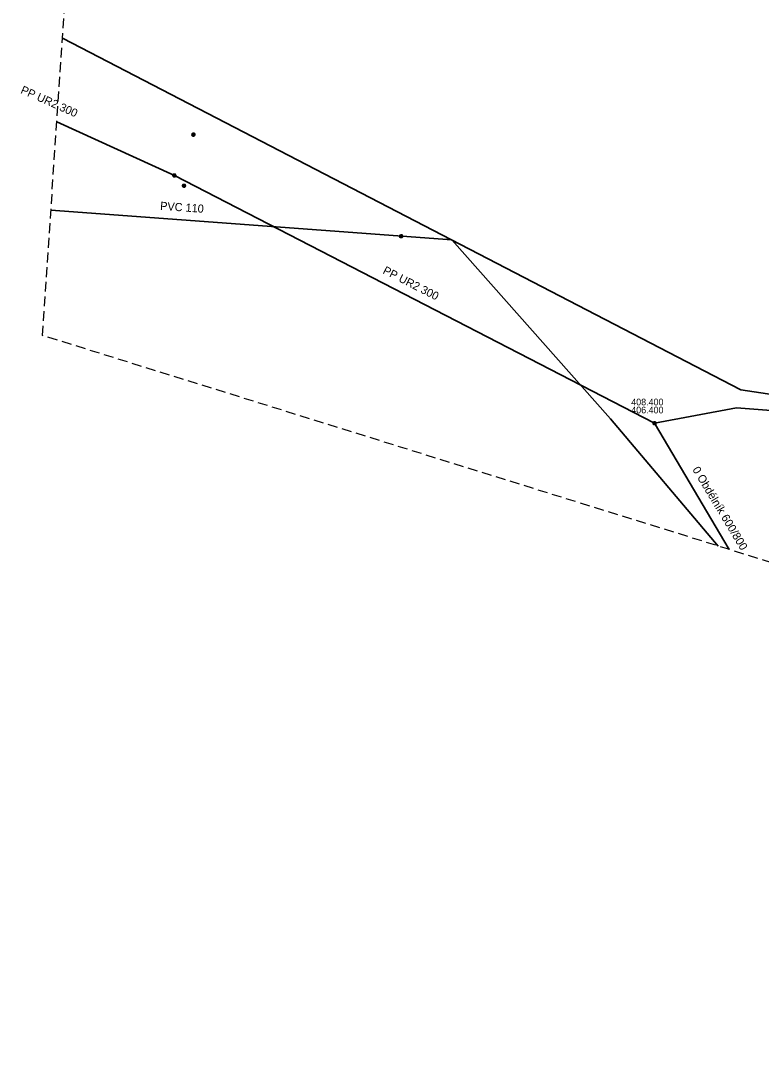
# Model space of a CAD drawing. Extents: x -867104 to -866746, y -1014489 to -1014255.
# Drawn here: x -867103.7 to -867003.8, y -1014488.9 to -1014348.8 of the extents above; entities that cross this region are included whole.
import ezdxf

# ---------------------------------------------------------------- set-up
doc = ezdxf.new("R2010")
doc.units = 0
doc.header["$LTSCALE"] = 0.44
doc.linetypes.add('MEDIUM_DASHED', pattern=[4.5, 3, -1.5])
for name, color, linetype, lineweight in [('1', 7, 'Continuous', 35), ('12', 7, 'Continuous', 13), ('21', 7, 'Continuous', 35), ('25', 7, 'Continuous', 13), ('32', 7, 'Continuous', 13), ('62', 7, 'MEDIUM_DASHED', 25)]:
    doc.layers.add(name, color=color, linetype=linetype, lineweight=lineweight)

msp = doc.modelspace()

# ---------------------------------------------------------------- linework, layer by layer
at = {"layer": '1'}
msp.add_line((-867045.534, -1014378.337), (-867099.611, -1014374.334), dxfattribs=at)
for points in [[(-866877.679, -1014463.149), (-866884.593, -1014451.356), (-866912.586, -1014412.658), (-867006.516, -1014398.571), (-867098.057, -1014351.101)], [(-867009.578, -1014419.65), (-867024.113, -1014402.496), (-867045.534, -1014378.337)]]:
    msp.add_lwpolyline(points, dxfattribs=at)
at = {"layer": '12'}
for points in [[(-867052.127, -1014377.832), (-867052.133, -1014377.78), (-867052.15, -1014377.73), (-867052.179, -1014377.686), (-867052.216, -1014377.649), (-867052.261, -1014377.622), (-867052.311, -1014377.605), (-867052.364, -1014377.601), (-867052.416, -1014377.608), (-867052.465, -1014377.627), (-867052.508, -1014377.656), (-867052.544, -1014377.695), (-867052.57, -1014377.74), (-867052.586, -1014377.791), (-867052.589, -1014377.843), (-867052.581, -1014377.895), (-867052.561, -1014377.944), (-867052.53, -1014377.987), (-867052.491, -1014378.021), (-867052.445, -1014378.047), (-867052.394, -1014378.061), (-867052.341, -1014378.063), (-867052.29, -1014378.053), (-867052.242, -1014378.032), (-867052.199, -1014378.001), (-867052.165, -1014377.96), (-867052.141, -1014377.914), (-867052.129, -1014377.863)], [(-867052.157, -1014377.832), (-867052.163, -1014377.783), (-867052.18, -1014377.737), (-867052.208, -1014377.697), (-867052.245, -1014377.665), (-867052.289, -1014377.643), (-867052.337, -1014377.632), (-867052.386, -1014377.632), (-867052.433, -1014377.645), (-867052.476, -1014377.669), (-867052.512, -1014377.702), (-867052.539, -1014377.743), (-867052.555, -1014377.79), (-867052.559, -1014377.839), (-867052.552, -1014377.887), (-867052.533, -1014377.932), (-867052.503, -1014377.972), (-867052.465, -1014378.003), (-867052.421, -1014378.023), (-867052.373, -1014378.033), (-867052.324, -1014378.031), (-867052.277, -1014378.016), (-867052.234, -1014377.991), (-867052.2, -1014377.957), (-867052.174, -1014377.915), (-867052.16, -1014377.868)], [(-867052.187, -1014377.832), (-867052.193, -1014377.787), (-867052.21, -1014377.745), (-867052.238, -1014377.71), (-867052.274, -1014377.683), (-867052.316, -1014377.666), (-867052.361, -1014377.661), (-867052.406, -1014377.667), (-867052.447, -1014377.686), (-867052.482, -1014377.714), (-867052.509, -1014377.751), (-867052.525, -1014377.793), (-867052.529, -1014377.838), (-867052.522, -1014377.883), (-867052.503, -1014377.924), (-867052.474, -1014377.958), (-867052.437, -1014377.984), (-867052.394, -1014378), (-867052.349, -1014378.003), (-867052.304, -1014377.995), (-867052.264, -1014377.975), (-867052.23, -1014377.946), (-867052.204, -1014377.908), (-867052.19, -1014377.865)], [(-867052.217, -1014377.832), (-867052.222, -1014377.791), (-867052.24, -1014377.754), (-867052.267, -1014377.723), (-867052.302, -1014377.702), (-867052.342, -1014377.691), (-867052.383, -1014377.693), (-867052.422, -1014377.706), (-867052.456, -1014377.73), (-867052.481, -1014377.762), (-867052.496, -1014377.8), (-867052.499, -1014377.841), (-867052.491, -1014377.881), (-867052.471, -1014377.917), (-867052.442, -1014377.946), (-867052.405, -1014377.965), (-867052.365, -1014377.973), (-867052.324, -1014377.969), (-867052.286, -1014377.954), (-867052.254, -1014377.928), (-867052.231, -1014377.894), (-867052.218, -1014377.855)], [(-867052.247, -1014377.832), (-867052.252, -1014377.796), (-867052.27, -1014377.764), (-867052.296, -1014377.739), (-867052.33, -1014377.724), (-867052.366, -1014377.721), (-867052.401, -1014377.729), (-867052.432, -1014377.749), (-867052.455, -1014377.777), (-867052.468, -1014377.811), (-867052.468, -1014377.848), (-867052.457, -1014377.883), (-867052.436, -1014377.912), (-867052.406, -1014377.933), (-867052.371, -1014377.943), (-867052.334, -1014377.941), (-867052.3, -1014377.927), (-867052.273, -1014377.904), (-867052.254, -1014377.872), (-867052.247, -1014377.837)], [(-867052.277, -1014377.832), (-867052.282, -1014377.801), (-867052.299, -1014377.775), (-867052.325, -1014377.758), (-867052.355, -1014377.751), (-867052.386, -1014377.755), (-867052.413, -1014377.772), (-867052.431, -1014377.796), (-867052.439, -1014377.827), (-867052.435, -1014377.857), (-867052.42, -1014377.885), (-867052.396, -1014377.904), (-867052.366, -1014377.913), (-867052.335, -1014377.91), (-867052.307, -1014377.896), (-867052.287, -1014377.872), (-867052.277, -1014377.843)], [(-867052.307, -1014377.832), (-867052.312, -1014377.808), (-867052.329, -1014377.79), (-867052.352, -1014377.781), (-867052.376, -1014377.784), (-867052.397, -1014377.798), (-867052.408, -1014377.82), (-867052.408, -1014377.845), (-867052.396, -1014377.866), (-867052.376, -1014377.88), (-867052.351, -1014377.883), (-867052.328, -1014377.874), (-867052.312, -1014377.856)], [(-867052.337, -1014377.832), (-867052.342, -1014377.817), (-867052.357, -1014377.811), (-867052.372, -1014377.815), (-867052.379, -1014377.829), (-867052.375, -1014377.844), (-867052.362, -1014377.853), (-867052.347, -1014377.85), (-867052.337, -1014377.838)]]:
    msp.add_lwpolyline(points, close=True, dxfattribs=at)
at = {"layer": '21'}
for p, q in [((-867082.957, -1014369.63), (-867098.814, -1014362.42)), ((-867018.151, -1014403.08), (-867082.957, -1014369.63)), ((-867008.073, -1014420.119), (-867018.151, -1014403.08))]:
    msp.add_line(p, q, dxfattribs=at)
msp.add_lwpolyline([(-866953.081, -1014405.138), (-866972.671, -1014403.647), (-866981.237, -1014402.954), (-866985.536, -1014402.661), (-867007.098, -1014400.979), (-867018.151, -1014403.08)], dxfattribs=at)
at = {"layer": '25'}
for points in [[(-867080.159, -1014364.13), (-867080.165, -1014364.078), (-867080.182, -1014364.028), (-867080.211, -1014363.984), (-867080.248, -1014363.947), (-867080.293, -1014363.92), (-867080.343, -1014363.903), (-867080.396, -1014363.899), (-867080.448, -1014363.906), (-867080.497, -1014363.925), (-867080.54, -1014363.954), (-867080.576, -1014363.993), (-867080.602, -1014364.038), (-867080.618, -1014364.089), (-867080.621, -1014364.141), (-867080.613, -1014364.193), (-867080.593, -1014364.242), (-867080.562, -1014364.285), (-867080.523, -1014364.319), (-867080.477, -1014364.345), (-867080.426, -1014364.359), (-867080.373, -1014364.361), (-867080.322, -1014364.351), (-867080.274, -1014364.33), (-867080.231, -1014364.299), (-867080.197, -1014364.258), (-867080.173, -1014364.212), (-867080.161, -1014364.161)], [(-867080.189, -1014364.13), (-867080.195, -1014364.081), (-867080.212, -1014364.035), (-867080.24, -1014363.995), (-867080.277, -1014363.963), (-867080.321, -1014363.941), (-867080.369, -1014363.93), (-867080.418, -1014363.93), (-867080.465, -1014363.943), (-867080.508, -1014363.967), (-867080.544, -1014364), (-867080.571, -1014364.041), (-867080.587, -1014364.088), (-867080.591, -1014364.137), (-867080.584, -1014364.185), (-867080.565, -1014364.23), (-867080.535, -1014364.27), (-867080.497, -1014364.301), (-867080.453, -1014364.321), (-867080.405, -1014364.331), (-867080.356, -1014364.329), (-867080.309, -1014364.314), (-867080.266, -1014364.289), (-867080.232, -1014364.255), (-867080.206, -1014364.213), (-867080.192, -1014364.166)], [(-867080.219, -1014364.13), (-867080.225, -1014364.085), (-867080.242, -1014364.043), (-867080.27, -1014364.008), (-867080.306, -1014363.981), (-867080.348, -1014363.964), (-867080.393, -1014363.959), (-867080.438, -1014363.965), (-867080.479, -1014363.984), (-867080.514, -1014364.012), (-867080.541, -1014364.049), (-867080.557, -1014364.091), (-867080.561, -1014364.136), (-867080.554, -1014364.181), (-867080.535, -1014364.222), (-867080.506, -1014364.256), (-867080.469, -1014364.282), (-867080.426, -1014364.298), (-867080.381, -1014364.301), (-867080.336, -1014364.293), (-867080.296, -1014364.273), (-867080.262, -1014364.244), (-867080.236, -1014364.206), (-867080.222, -1014364.163)], [(-867080.249, -1014364.13), (-867080.254, -1014364.089), (-867080.272, -1014364.052), (-867080.299, -1014364.021), (-867080.334, -1014364), (-867080.374, -1014363.989), (-867080.415, -1014363.991), (-867080.454, -1014364.004), (-867080.488, -1014364.028), (-867080.513, -1014364.06), (-867080.528, -1014364.098), (-867080.531, -1014364.139), (-867080.523, -1014364.179), (-867080.503, -1014364.215), (-867080.474, -1014364.244), (-867080.437, -1014364.263), (-867080.397, -1014364.271), (-867080.356, -1014364.267), (-867080.318, -1014364.252), (-867080.286, -1014364.226), (-867080.263, -1014364.192), (-867080.25, -1014364.153)], [(-867080.279, -1014364.13), (-867080.284, -1014364.094), (-867080.302, -1014364.062), (-867080.328, -1014364.037), (-867080.362, -1014364.022), (-867080.398, -1014364.019), (-867080.433, -1014364.027), (-867080.464, -1014364.047), (-867080.487, -1014364.075), (-867080.5, -1014364.109), (-867080.5, -1014364.146), (-867080.489, -1014364.181), (-867080.468, -1014364.21), (-867080.438, -1014364.231), (-867080.403, -1014364.241), (-867080.366, -1014364.239), (-867080.332, -1014364.225), (-867080.305, -1014364.202), (-867080.286, -1014364.17), (-867080.279, -1014364.135)], [(-867080.309, -1014364.13), (-867080.314, -1014364.099), (-867080.331, -1014364.073), (-867080.357, -1014364.056), (-867080.387, -1014364.049), (-867080.418, -1014364.053), (-867080.445, -1014364.07), (-867080.463, -1014364.094), (-867080.471, -1014364.125), (-867080.467, -1014364.155), (-867080.452, -1014364.183), (-867080.428, -1014364.202), (-867080.398, -1014364.211), (-867080.367, -1014364.208), (-867080.339, -1014364.194), (-867080.319, -1014364.17), (-867080.309, -1014364.141)], [(-867080.339, -1014364.13), (-867080.344, -1014364.106), (-867080.361, -1014364.088), (-867080.384, -1014364.079), (-867080.408, -1014364.082), (-867080.429, -1014364.096), (-867080.44, -1014364.118), (-867080.44, -1014364.143), (-867080.428, -1014364.164), (-867080.408, -1014364.178), (-867080.383, -1014364.181), (-867080.36, -1014364.172), (-867080.344, -1014364.154)], [(-867080.369, -1014364.13), (-867080.374, -1014364.115), (-867080.389, -1014364.109), (-867080.404, -1014364.113), (-867080.411, -1014364.127), (-867080.407, -1014364.142), (-867080.394, -1014364.151), (-867080.379, -1014364.148), (-867080.369, -1014364.136)], [(-867081.419, -1014371.02), (-867081.425, -1014370.968), (-867081.442, -1014370.918), (-867081.471, -1014370.874), (-867081.508, -1014370.837), (-867081.553, -1014370.81), (-867081.603, -1014370.793), (-867081.656, -1014370.789), (-867081.708, -1014370.796), (-867081.757, -1014370.815), (-867081.8, -1014370.844), (-867081.836, -1014370.883), (-867081.862, -1014370.928), (-867081.878, -1014370.979), (-867081.881, -1014371.031), (-867081.873, -1014371.083), (-867081.853, -1014371.132), (-867081.822, -1014371.175), (-867081.783, -1014371.209), (-867081.737, -1014371.235), (-867081.686, -1014371.249), (-867081.633, -1014371.251), (-867081.582, -1014371.241), (-867081.534, -1014371.22), (-867081.491, -1014371.189), (-867081.457, -1014371.148), (-867081.433, -1014371.102), (-867081.421, -1014371.051)], [(-867081.449, -1014371.02), (-867081.455, -1014370.971), (-867081.472, -1014370.925), (-867081.5, -1014370.885), (-867081.537, -1014370.853), (-867081.581, -1014370.831), (-867081.629, -1014370.82), (-867081.678, -1014370.82), (-867081.725, -1014370.833), (-867081.768, -1014370.857), (-867081.804, -1014370.89), (-867081.831, -1014370.931), (-867081.847, -1014370.978), (-867081.851, -1014371.027), (-867081.844, -1014371.075), (-867081.825, -1014371.12), (-867081.795, -1014371.16), (-867081.757, -1014371.191), (-867081.713, -1014371.211), (-867081.665, -1014371.221), (-867081.616, -1014371.219), (-867081.569, -1014371.204), (-867081.526, -1014371.179), (-867081.492, -1014371.145), (-867081.466, -1014371.103), (-867081.452, -1014371.056)], [(-867081.479, -1014371.02), (-867081.485, -1014370.975), (-867081.502, -1014370.933), (-867081.53, -1014370.898), (-867081.566, -1014370.871), (-867081.608, -1014370.854), (-867081.653, -1014370.849), (-867081.698, -1014370.855), (-867081.739, -1014370.874), (-867081.774, -1014370.902), (-867081.801, -1014370.939), (-867081.817, -1014370.981), (-867081.821, -1014371.026), (-867081.814, -1014371.071), (-867081.795, -1014371.112), (-867081.766, -1014371.146), (-867081.729, -1014371.172), (-867081.686, -1014371.188), (-867081.641, -1014371.191), (-867081.596, -1014371.183), (-867081.556, -1014371.163), (-867081.522, -1014371.134), (-867081.496, -1014371.096), (-867081.482, -1014371.053)], [(-867081.509, -1014371.02), (-867081.514, -1014370.979), (-867081.532, -1014370.942), (-867081.559, -1014370.911), (-867081.594, -1014370.89), (-867081.634, -1014370.879), (-867081.675, -1014370.881), (-867081.714, -1014370.894), (-867081.748, -1014370.918), (-867081.773, -1014370.95), (-867081.788, -1014370.988), (-867081.791, -1014371.029), (-867081.783, -1014371.069), (-867081.763, -1014371.105), (-867081.734, -1014371.134), (-867081.697, -1014371.153), (-867081.657, -1014371.161), (-867081.616, -1014371.157), (-867081.578, -1014371.142), (-867081.546, -1014371.116), (-867081.523, -1014371.082), (-867081.51, -1014371.043)], [(-867081.539, -1014371.02), (-867081.544, -1014370.984), (-867081.562, -1014370.952), (-867081.588, -1014370.927), (-867081.622, -1014370.912), (-867081.658, -1014370.909), (-867081.693, -1014370.917), (-867081.724, -1014370.937), (-867081.747, -1014370.965), (-867081.76, -1014370.999), (-867081.76, -1014371.036), (-867081.749, -1014371.071), (-867081.728, -1014371.1), (-867081.698, -1014371.121), (-867081.663, -1014371.131), (-867081.626, -1014371.129), (-867081.592, -1014371.115), (-867081.565, -1014371.092), (-867081.546, -1014371.06), (-867081.539, -1014371.025)], [(-867081.569, -1014371.02), (-867081.574, -1014370.989), (-867081.591, -1014370.963), (-867081.617, -1014370.946), (-867081.647, -1014370.939), (-867081.678, -1014370.943), (-867081.705, -1014370.96), (-867081.723, -1014370.984), (-867081.731, -1014371.015), (-867081.727, -1014371.045), (-867081.712, -1014371.073), (-867081.688, -1014371.092), (-867081.658, -1014371.101), (-867081.627, -1014371.098), (-867081.599, -1014371.084), (-867081.579, -1014371.06), (-867081.569, -1014371.031)], [(-867081.599, -1014371.02), (-867081.604, -1014370.996), (-867081.621, -1014370.978), (-867081.644, -1014370.969), (-867081.668, -1014370.972), (-867081.689, -1014370.986), (-867081.7, -1014371.008), (-867081.7, -1014371.033), (-867081.688, -1014371.054), (-867081.668, -1014371.068), (-867081.643, -1014371.071), (-867081.62, -1014371.062), (-867081.604, -1014371.044)], [(-867081.629, -1014371.02), (-867081.634, -1014371.005), (-867081.649, -1014370.999), (-867081.664, -1014371.003), (-867081.671, -1014371.017), (-867081.667, -1014371.032), (-867081.654, -1014371.041), (-867081.639, -1014371.038), (-867081.629, -1014371.026)]]:
    msp.add_lwpolyline(points, close=True, dxfattribs=at)
at = {"layer": '32'}
for points in [[(-867082.726, -1014369.63), (-867082.732, -1014369.578), (-867082.749, -1014369.528), (-867082.778, -1014369.484), (-867082.815, -1014369.447), (-867082.86, -1014369.42), (-867082.91, -1014369.403), (-867082.963, -1014369.399), (-867083.015, -1014369.406), (-867083.064, -1014369.425), (-867083.107, -1014369.454), (-867083.143, -1014369.493), (-867083.169, -1014369.538), (-867083.185, -1014369.589), (-867083.188, -1014369.641), (-867083.18, -1014369.693), (-867083.16, -1014369.742), (-867083.129, -1014369.785), (-867083.09, -1014369.819), (-867083.044, -1014369.845), (-867082.993, -1014369.859), (-867082.94, -1014369.861), (-867082.889, -1014369.851), (-867082.841, -1014369.83), (-867082.798, -1014369.799), (-867082.764, -1014369.758), (-867082.74, -1014369.712), (-867082.728, -1014369.661)], [(-867082.756, -1014369.63), (-867082.762, -1014369.581), (-867082.779, -1014369.535), (-867082.807, -1014369.495), (-867082.844, -1014369.463), (-867082.888, -1014369.441), (-867082.936, -1014369.43), (-867082.985, -1014369.43), (-867083.032, -1014369.443), (-867083.075, -1014369.467), (-867083.111, -1014369.5), (-867083.138, -1014369.541), (-867083.154, -1014369.588), (-867083.158, -1014369.637), (-867083.151, -1014369.685), (-867083.132, -1014369.73), (-867083.102, -1014369.77), (-867083.064, -1014369.801), (-867083.02, -1014369.821), (-867082.972, -1014369.831), (-867082.923, -1014369.829), (-867082.876, -1014369.814), (-867082.833, -1014369.789), (-867082.799, -1014369.755), (-867082.773, -1014369.713), (-867082.759, -1014369.666)], [(-867082.786, -1014369.63), (-867082.792, -1014369.585), (-867082.809, -1014369.543), (-867082.837, -1014369.508), (-867082.873, -1014369.481), (-867082.915, -1014369.464), (-867082.96, -1014369.459), (-867083.005, -1014369.465), (-867083.046, -1014369.484), (-867083.081, -1014369.512), (-867083.108, -1014369.549), (-867083.124, -1014369.591), (-867083.128, -1014369.636), (-867083.121, -1014369.681), (-867083.102, -1014369.722), (-867083.073, -1014369.756), (-867083.036, -1014369.782), (-867082.993, -1014369.798), (-867082.948, -1014369.801), (-867082.903, -1014369.793), (-867082.863, -1014369.773), (-867082.829, -1014369.744), (-867082.803, -1014369.706), (-867082.789, -1014369.663)], [(-867082.816, -1014369.63), (-867082.821, -1014369.589), (-867082.839, -1014369.552), (-867082.866, -1014369.521), (-867082.901, -1014369.5), (-867082.941, -1014369.489), (-867082.982, -1014369.491), (-867083.021, -1014369.504), (-867083.055, -1014369.528), (-867083.08, -1014369.56), (-867083.095, -1014369.598), (-867083.098, -1014369.639), (-867083.09, -1014369.679), (-867083.07, -1014369.715), (-867083.041, -1014369.744), (-867083.004, -1014369.763), (-867082.964, -1014369.771), (-867082.923, -1014369.767), (-867082.885, -1014369.752), (-867082.853, -1014369.726), (-867082.83, -1014369.692), (-867082.817, -1014369.653)], [(-867082.846, -1014369.63), (-867082.851, -1014369.594), (-867082.869, -1014369.562), (-867082.895, -1014369.537), (-867082.929, -1014369.522), (-867082.965, -1014369.519), (-867083, -1014369.527), (-867083.031, -1014369.547), (-867083.054, -1014369.575), (-867083.067, -1014369.609), (-867083.067, -1014369.646), (-867083.056, -1014369.681), (-867083.035, -1014369.71), (-867083.005, -1014369.731), (-867082.97, -1014369.741), (-867082.933, -1014369.739), (-867082.899, -1014369.725), (-867082.872, -1014369.702), (-867082.853, -1014369.67), (-867082.846, -1014369.635)], [(-867082.876, -1014369.63), (-867082.881, -1014369.599), (-867082.898, -1014369.573), (-867082.924, -1014369.556), (-867082.954, -1014369.549), (-867082.985, -1014369.553), (-867083.012, -1014369.57), (-867083.03, -1014369.594), (-867083.038, -1014369.625), (-867083.034, -1014369.655), (-867083.019, -1014369.683), (-867082.995, -1014369.702), (-867082.965, -1014369.711), (-867082.934, -1014369.708), (-867082.906, -1014369.694), (-867082.886, -1014369.67), (-867082.876, -1014369.641)], [(-867082.906, -1014369.63), (-867082.911, -1014369.606), (-867082.928, -1014369.588), (-867082.951, -1014369.579), (-867082.975, -1014369.582), (-867082.996, -1014369.596), (-867083.007, -1014369.618), (-867083.007, -1014369.643), (-867082.995, -1014369.664), (-867082.975, -1014369.678), (-867082.95, -1014369.681), (-867082.927, -1014369.672), (-867082.911, -1014369.654)], [(-867082.936, -1014369.63), (-867082.941, -1014369.615), (-867082.956, -1014369.609), (-867082.971, -1014369.613), (-867082.978, -1014369.627), (-867082.974, -1014369.642), (-867082.961, -1014369.651), (-867082.946, -1014369.648), (-867082.936, -1014369.636)], [(-867017.919, -1014403.08), (-867017.926, -1014403.028), (-867017.943, -1014402.978), (-867017.972, -1014402.934), (-867018.009, -1014402.897), (-867018.054, -1014402.87), (-867018.103, -1014402.853), (-867018.157, -1014402.849), (-867018.208, -1014402.856), (-867018.257, -1014402.875), (-867018.301, -1014402.904), (-867018.337, -1014402.943), (-867018.363, -1014402.988), (-867018.379, -1014403.039), (-867018.382, -1014403.091), (-867018.374, -1014403.143), (-867018.353, -1014403.192), (-867018.323, -1014403.235), (-867018.284, -1014403.269), (-867018.238, -1014403.295), (-867018.186, -1014403.309), (-867018.134, -1014403.311), (-867018.083, -1014403.301), (-867018.034, -1014403.28), (-867017.992, -1014403.249), (-867017.958, -1014403.208), (-867017.934, -1014403.162), (-867017.921, -1014403.111)], [(-867017.95, -1014403.08), (-867017.956, -1014403.031), (-867017.973, -1014402.985), (-867018, -1014402.945), (-867018.038, -1014402.913), (-867018.081, -1014402.891), (-867018.13, -1014402.88), (-867018.179, -1014402.88), (-867018.225, -1014402.893), (-867018.269, -1014402.917), (-867018.304, -1014402.95), (-867018.331, -1014402.991), (-867018.348, -1014403.038), (-867018.352, -1014403.087), (-867018.345, -1014403.135), (-867018.326, -1014403.18), (-867018.296, -1014403.22), (-867018.257, -1014403.251), (-867018.213, -1014403.271), (-867018.166, -1014403.281), (-867018.117, -1014403.279), (-867018.07, -1014403.264), (-867018.027, -1014403.239), (-867017.992, -1014403.205), (-867017.967, -1014403.163), (-867017.953, -1014403.116)], [(-867017.98, -1014403.08), (-867017.985, -1014403.035), (-867018.002, -1014402.993), (-867018.031, -1014402.958), (-867018.066, -1014402.931), (-867018.108, -1014402.914), (-867018.154, -1014402.909), (-867018.198, -1014402.915), (-867018.24, -1014402.934), (-867018.274, -1014402.962), (-867018.301, -1014402.999), (-867018.318, -1014403.041), (-867018.321, -1014403.086), (-867018.315, -1014403.131), (-867018.296, -1014403.172), (-867018.267, -1014403.206), (-867018.23, -1014403.232), (-867018.186, -1014403.248), (-867018.142, -1014403.251), (-867018.097, -1014403.243), (-867018.056, -1014403.223), (-867018.022, -1014403.194), (-867017.997, -1014403.156), (-867017.983, -1014403.113)], [(-867018.01, -1014403.08), (-867018.014, -1014403.039), (-867018.032, -1014403.002), (-867018.059, -1014402.971), (-867018.095, -1014402.95), (-867018.135, -1014402.939), (-867018.176, -1014402.941), (-867018.215, -1014402.954), (-867018.249, -1014402.978), (-867018.274, -1014403.01), (-867018.289, -1014403.048), (-867018.291, -1014403.089), (-867018.284, -1014403.129), (-867018.264, -1014403.165), (-867018.235, -1014403.194), (-867018.198, -1014403.213), (-867018.157, -1014403.221), (-867018.117, -1014403.217), (-867018.078, -1014403.202), (-867018.046, -1014403.176), (-867018.024, -1014403.142), (-867018.011, -1014403.103)], [(-867018.039, -1014403.08), (-867018.044, -1014403.044), (-867018.063, -1014403.012), (-867018.088, -1014402.987), (-867018.122, -1014402.972), (-867018.159, -1014402.969), (-867018.193, -1014402.977), (-867018.225, -1014402.997), (-867018.247, -1014403.025), (-867018.261, -1014403.059), (-867018.261, -1014403.096), (-867018.25, -1014403.131), (-867018.228, -1014403.16), (-867018.198, -1014403.181), (-867018.164, -1014403.191), (-867018.127, -1014403.189), (-867018.093, -1014403.175), (-867018.066, -1014403.152), (-867018.046, -1014403.12), (-867018.039, -1014403.085)], [(-867018.07, -1014403.08), (-867018.075, -1014403.049), (-867018.092, -1014403.023), (-867018.117, -1014403.006), (-867018.147, -1014402.999), (-867018.179, -1014403.003), (-867018.206, -1014403.02), (-867018.223, -1014403.044), (-867018.232, -1014403.075), (-867018.228, -1014403.105), (-867018.213, -1014403.133), (-867018.188, -1014403.152), (-867018.159, -1014403.161), (-867018.127, -1014403.158), (-867018.1, -1014403.144), (-867018.08, -1014403.12), (-867018.07, -1014403.091)], [(-867018.1, -1014403.08), (-867018.105, -1014403.056), (-867018.122, -1014403.038), (-867018.144, -1014403.029), (-867018.169, -1014403.032), (-867018.19, -1014403.046), (-867018.201, -1014403.068), (-867018.201, -1014403.093), (-867018.188, -1014403.114), (-867018.169, -1014403.128), (-867018.144, -1014403.131), (-867018.12, -1014403.122), (-867018.105, -1014403.104)], [(-867018.13, -1014403.08), (-867018.135, -1014403.065), (-867018.149, -1014403.059), (-867018.164, -1014403.063), (-867018.171, -1014403.077), (-867018.168, -1014403.092), (-867018.154, -1014403.101), (-867018.139, -1014403.098), (-867018.13, -1014403.086)]]:
    msp.add_lwpolyline(points, close=True, dxfattribs=at)
at = {"layer": '62'}
msp.add_lwpolyline([(-867100.742, -1014391.242), (-867092.704, -1014271.063), (-867058.137, -1014262.221), (-866832.652, -1014254.584), (-866798.889, -1014276.691), (-866769.95, -1014301.209), (-866746.236, -1014362.705), (-866806.526, -1014433.445), (-866883.697, -1014488.912), (-866958.859, -1014435.455)], close=True, dxfattribs=at)

# ---------------------------------------------------------------- texts
at = {"layer": '1'}
for s, rotation, p in [('PP UR2 300', 336, (-867103.789, -1014358.483)), ('PVC 110 ', 356, (-867084.9, -1014374.27)), ('PP UR2 300', 333, (-867054.913, -1014382.81)), ('0 Obdélník 600/800', 301, (-867013.089, -1014409.332))]:
    msp.add_text(s, height=1.1, rotation=rotation, dxfattribs=at).set_placement(p)
for s, p in [('408.400 ', (-867021.3, -1014400.663)), ('406.400 ', (-867021.3, -1014401.74))]:
    msp.add_text(s, height=0.9, dxfattribs=at).set_placement(p)

doc.saveas('drawing.dxf')
